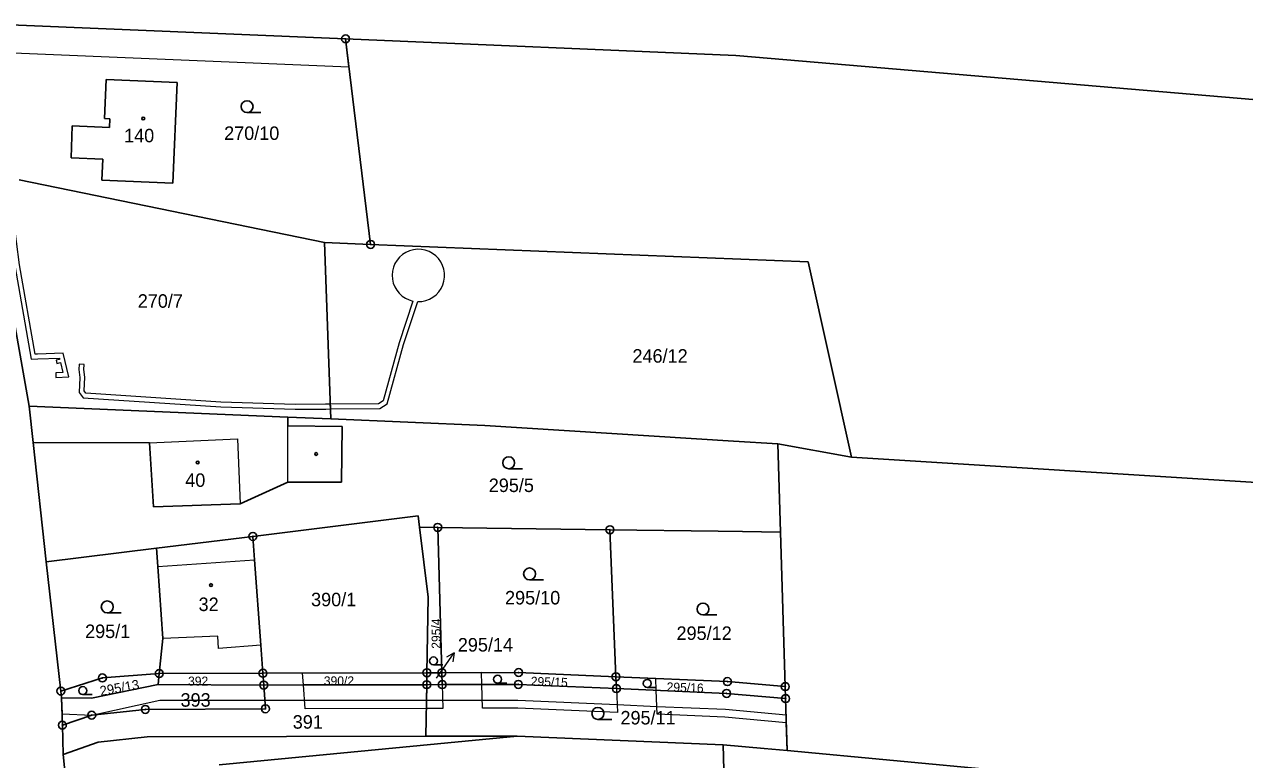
# Model space of a CAD drawing. Extents: x -645290 to -643454, y -1064771 to -1062356.
# Drawn here: x -644577 to -644423.3, y -1063574.3 to -1063481.7 of the extents above; entities that cross this region are included whole.
import ezdxf
from ezdxf.enums import TextEntityAlignment as Align

# ---------------------------------------------------------------- set-up
doc = ezdxf.new("R2010")
doc.units = 0
doc.header["$LTSCALE"] = 0.68
for name, color, linetype, lineweight in [('1', 7, 'Continuous', 25), ('13', 7, 'Continuous', 13), ('3', 7, 'Continuous', 25), ('4', 7, 'Continuous', 13), ('5', 7, 'Continuous', 25), ('7', 7, 'Continuous', 13), ('8', 7, 'Continuous', 25)]:
    doc.layers.add(name, color=color, linetype=linetype, lineweight=lineweight)
doc.layers.add('2', color=7, linetype='Continuous')

msp = doc.modelspace()

# ---------------------------------------------------------------- linework, layer by layer
at = {"layer": '1'}
for p, q in [((-644579.79, -1063481.67), (-644536.58, -1063483.49)), ((-644536.58, -1063483.49), (-644533.43, -1063509.39)), ((-644536.58, -1063483.49), (-644487.41, -1063485.57)), ((-644487.41, -1063485.57), (-644392.24, -1063493.71)), ((-644566.96, -1063493.51), (-644566.75, -1063488.62)), ((-644566.75, -1063488.62), (-644557.79, -1063489)), ((-644557.79, -1063489), (-644558.32, -1063501.68)), ((-644566.27, -1063493.55), (-644566.96, -1063493.51)), ((-644566.32, -1063494.66), (-644566.27, -1063493.55)), ((-644571.15, -1063498.5), (-644571.01, -1063494.45)), ((-644571.01, -1063494.45), (-644566.32, -1063494.66)), ((-644567.16, -1063498.66), (-644571.15, -1063498.5)), ((-644567.29, -1063501.28), (-644567.16, -1063498.66)), ((-644577.69, -1063501.25), (-644539.22, -1063509.16)), ((-644558.32, -1063501.68), (-644567.29, -1063501.28)), ((-644580.6, -1063506.24), (-644576.45, -1063529.78)), ((-644533.43, -1063509.39), (-644539.22, -1063509.16)), ((-644539.22, -1063509.16), (-644538.44, -1063531.37)), ((-644478.32, -1063511.57), (-644533.43, -1063509.39)), ((-644472.86, -1063536.21), (-644478.32, -1063511.57)), ((-644576.45, -1063529.78), (-644575.94, -1063534.35)), ((-644543.84, -1063531.14), (-644576.45, -1063529.78)), ((-644543.85, -1063532.23), (-644543.84, -1063531.14)), ((-644536.99, -1063532.32), (-644543.85, -1063532.23)), ((-644538.44, -1063531.37), (-644543.84, -1063531.14)), ((-644538.44, -1063531.37), (-644519.04, -1063532.18)), ((-644537.08, -1063539.34), (-644536.99, -1063532.32)), ((-644519.04, -1063532.18), (-644487.72, -1063534.16)), ((-644575.94, -1063534.35), (-644574.28, -1063549.38)), ((-644575.94, -1063534.35), (-644561.26, -1063534.39)), ((-644561.26, -1063534.39), (-644560.78, -1063542.45)), ((-644482.13, -1063534.51), (-644487.72, -1063534.16)), ((-644482.13, -1063534.51), (-644472.86, -1063536.21)), ((-644482.13, -1063534.51), (-644481.79, -1063545.62)), ((-644472.86, -1063536.21), (-644385.25, -1063541.67)), ((-644549.86, -1063542.06), (-644543.86, -1063539.32)), ((-644543.86, -1063539.32), (-644537.08, -1063539.34)), ((-644560.78, -1063542.45), (-644549.86, -1063542.06)), ((-644548.26, -1063546.17), (-644527.42, -1063543.6)), ((-644527.42, -1063543.6), (-644527.25, -1063545.01)), ((-644527.25, -1063545.01), (-644526.18, -1063553.83)), ((-644527.25, -1063545.01), (-644524.97, -1063545.04)), ((-644524.45, -1063563.34), (-644524.97, -1063545.04)), ((-644524.97, -1063545.04), (-644503.29, -1063545.33)), ((-644503.29, -1063545.33), (-644502.53, -1063563.85)), ((-644503.29, -1063545.33), (-644489.67, -1063545.52)), ((-644481.2, -1063565.1), (-644481.79, -1063545.62)), ((-644574.28, -1063549.38), (-644560.39, -1063547.67)), ((-644560.39, -1063547.67), (-644548.26, -1063546.17)), ((-644560.23, -1063549.96), (-644560.39, -1063547.67)), ((-644548.26, -1063546.17), (-644548.04, -1063549.14)), ((-644548.04, -1063549.14), (-644547.25, -1063559.89)), ((-644559.59, -1063559.05), (-644560.23, -1063549.96)), ((-644526.33, -1063563.35), (-644526.18, -1063553.83)), ((-644560.04, -1063563.44), (-644559.59, -1063559.05)), ((-644546.99, -1063563.41), (-644547.25, -1063559.89)), ((-644572.44, -1063565.65), (-644567.21, -1063564)), ((-644567.21, -1063564), (-644560.04, -1063563.44)), ((-644560.18, -1063564.82), (-644560.04, -1063563.44)), ((-644560.04, -1063563.44), (-644546.99, -1063563.41)), ((-644546.99, -1063563.41), (-644526.33, -1063563.35)), ((-644546.89, -1063564.9), (-644546.99, -1063563.41)), ((-644526.36, -1063564.85), (-644526.33, -1063563.35)), ((-644526.33, -1063563.35), (-644524.45, -1063563.34)), ((-644524.45, -1063563.34), (-644514.79, -1063563.32)), ((-644524.4, -1063564.84), (-644524.45, -1063563.34)), ((-644514.79, -1063563.32), (-644502.53, -1063563.85)), ((-644502.53, -1063563.85), (-644502.47, -1063565.35)), ((-644502.53, -1063563.85), (-644488.48, -1063564.46)), ((-644488.48, -1063564.46), (-644481.2, -1063565.1)), ((-644568.58, -1063566.54), (-644560.18, -1063564.82)), ((-644560.18, -1063564.82), (-644546.89, -1063564.9)), ((-644546.89, -1063564.9), (-644526.36, -1063564.85)), ((-644546.67, -1063567.89), (-644546.89, -1063564.9)), ((-644526.46, -1063571.35), (-644526.36, -1063564.85)), ((-644526.36, -1063564.85), (-644524.4, -1063564.84)), ((-644524.4, -1063564.84), (-644514.82, -1063564.82)), ((-644514.82, -1063564.82), (-644502.47, -1063565.35)), ((-644502.47, -1063565.35), (-644488.59, -1063565.95)), ((-644488.59, -1063565.95), (-644481.16, -1063566.61)), ((-644481.16, -1063566.61), (-644481.2, -1063565.1)), ((-644572.34, -1063566.51), (-644568.58, -1063566.54)), ((-644572.34, -1063566.51), (-644572.25, -1063569.95)), ((-644480.96, -1063573.16), (-644481.16, -1063566.61)), ((-644572.25, -1063569.95), (-644568.55, -1063568.69)), ((-644568.55, -1063568.69), (-644561.8, -1063567.97)), ((-644561.8, -1063567.97), (-644546.67, -1063567.89)), ((-644572.25, -1063569.95), (-644572.16, -1063573.65)), ((-644572.16, -1063573.65), (-644567.73, -1063572.1)), ((-644567.73, -1063572.1), (-644561.58, -1063571.44)), ((-644561.58, -1063571.44), (-644526.46, -1063571.35)), ((-644552.52, -1063574.93), (-644514.96, -1063571.32)), ((-644526.46, -1063571.35), (-644514.96, -1063571.32)), ((-644514.96, -1063571.32), (-644489.03, -1063572.44)), ((-644572.16, -1063573.65), (-644570.58, -1063588.42)), ((-644488.95, -1063575.57), (-644489.03, -1063572.44)), ((-644489.03, -1063572.44), (-644483.85, -1063572.9)), ((-644480.96, -1063573.16), (-644483.85, -1063572.9)), ((-644480.96, -1063573.16), (-644454.17, -1063575.65))]:
    msp.add_line(p, q, dxfattribs=at)
for points in [[(-644489.67, -1063545.52), (-644486.58, -1063545.56), (-644481.79, -1063545.62)], [(-644572.34, -1063566.51), (-644572.44, -1063565.65), (-644574.28, -1063549.38)]]:
    msp.add_lwpolyline(points, dxfattribs=at)
at = {"layer": '13'}
for points in [[(-644536.58, -1063483.49), (-644579.79, -1063481.67), (-644579.41, -1063485.19), (-644536.15, -1063487.01)], [(-644578.8, -1063503.15), (-644579.29, -1063503.99), (-644578.24, -1063512.03), (-644576.17, -1063523.83), (-644575.34, -1063523.8), (-644572.63, -1063523.71), (-644572.59, -1063523.88), (-644573.02, -1063523.99), (-644572.93, -1063524.37), (-644572.5, -1063524.26), (-644572.2, -1063525.52), (-644573.09, -1063525.56), (-644573.07, -1063526.16), (-644571.44, -1063526.09), (-644572.16, -1063523.09), (-644575.39, -1063523.2), (-644575.67, -1063523.21), (-644577.64, -1063511.94)], [(-644529.85, -1063521.8), (-644531.86, -1063529.08), (-644532.44, -1063529.47), (-644538.5, -1063529.52), (-644538.48, -1063530.12), (-644532.25, -1063530.07), (-644531.34, -1063529.45), (-644529.27, -1063521.98), (-644527.48, -1063516.59), (-644526.978, -1063516.562), (-644526.486, -1063516.459), (-644526.016, -1063516.282), (-644525.578, -1063516.035), (-644525.183, -1063515.725), (-644524.839, -1063515.359), (-644524.555, -1063514.944), (-644524.337, -1063514.492), (-644524.19, -1063514.011), (-644524.118, -1063513.514), (-644524.122, -1063513.011), (-644524.203, -1063512.515), (-644524.357, -1063512.037), (-644524.583, -1063511.588), (-644524.874, -1063511.179), (-644525.224, -1063510.818), (-644525.625, -1063510.515), (-644526.067, -1063510.276), (-644526.541, -1063510.107), (-644527.034, -1063510.012), (-644527.536, -1063509.993), (-644528.036, -1063510.05), (-644528.52, -1063510.183), (-644528.979, -1063510.387), (-644529.402, -1063510.659), (-644529.778, -1063510.992), (-644530.1, -1063511.378), (-644530.359, -1063511.809), (-644530.55, -1063512.274), (-644530.668, -1063512.762), (-644530.711, -1063513.263), (-644530.676, -1063513.764), (-644530.567, -1063514.255), (-644530.384, -1063514.723), (-644530.132, -1063515.157), (-644529.817, -1063515.549), (-644529.446, -1063515.888), (-644529.028, -1063516.167), (-644528.572, -1063516.379), (-644528.09, -1063516.52)], [(-644570.12, -1063524.48), (-644570.16, -1063525.16), (-644570.03, -1063526.15), (-644570.13, -1063528.04), (-644569.62, -1063528.7), (-644552.3, -1063529.85), (-644542.94, -1063530.16), (-644539.06, -1063530.13), (-644538.48, -1063530.12), (-644538.5, -1063529.52), (-644539.1, -1063529.53), (-644542.94, -1063529.56), (-644552.27, -1063529.25), (-644569.3, -1063528.12), (-644569.52, -1063527.85), (-644569.43, -1063526.13), (-644569.56, -1063525.14), (-644569.52, -1063524.52)], [(-644502.38, -1063567.36), (-644497.37, -1063567.58), (-644488.72, -1063567.95), (-644481.1, -1063568.63), (-644481.16, -1063566.61), (-644488.59, -1063565.95), (-644497.46, -1063565.57), (-644502.47, -1063565.35), (-644514.82, -1063564.82), (-644519.4, -1063564.83), (-644519.44, -1063563.33), (-644524.45, -1063563.34), (-644524.4, -1063564.84), (-644526.36, -1063564.85), (-644541.88, -1063564.89), (-644546.89, -1063564.9), (-644560.18, -1063564.82), (-644568.58, -1063566.54), (-644572.34, -1063566.51), (-644572.29, -1063568.51), (-644568.55, -1063568.69), (-644559.99, -1063566.82), (-644546.75, -1063566.82), (-644541.73, -1063566.82), (-644526.39, -1063566.82), (-644524.35, -1063566.82), (-644519.35, -1063566.82), (-644514.87, -1063566.82)], [(-644559.99, -1063566.82), (-644546.75, -1063566.82), (-644541.73, -1063566.82), (-644526.39, -1063566.82), (-644526.36, -1063564.85), (-644541.88, -1063564.89), (-644541.99, -1063563.4), (-644546.99, -1063563.41), (-644546.89, -1063564.9), (-644560.18, -1063564.82), (-644568.58, -1063566.54), (-644572.34, -1063566.51), (-644572.29, -1063568.51), (-644568.55, -1063568.69)], [(-644497.52, -1063564.07), (-644502.53, -1063563.85), (-644502.47, -1063565.35), (-644514.82, -1063564.82), (-644519.4, -1063564.83), (-644524.4, -1063564.84), (-644526.36, -1063564.85), (-644541.88, -1063564.89), (-644546.89, -1063564.9), (-644560.18, -1063564.82), (-644568.58, -1063566.54), (-644572.34, -1063566.51), (-644572.29, -1063568.51), (-644568.55, -1063568.69), (-644559.99, -1063566.82), (-644546.75, -1063566.82), (-644541.73, -1063566.82), (-644526.39, -1063566.82), (-644524.35, -1063566.82), (-644519.35, -1063566.82), (-644514.87, -1063566.82), (-644502.38, -1063567.36), (-644497.37, -1063567.58), (-644488.72, -1063567.95), (-644481.1, -1063568.63), (-644481.16, -1063566.61), (-644488.59, -1063565.95), (-644497.46, -1063565.57)], [(-644519.32, -1063567.83), (-644519.4, -1063564.83), (-644519.44, -1063563.33), (-644524.45, -1063563.34), (-644524.4, -1063564.84), (-644524.32, -1063567.84), (-644526.4, -1063567.85), (-644541.65, -1063567.88), (-644541.88, -1063564.89), (-644546.89, -1063564.9), (-644546.67, -1063567.89), (-644561.8, -1063567.97), (-644568.55, -1063568.69), (-644572.25, -1063569.95), (-644572.16, -1063573.65), (-644567.73, -1063572.1), (-644561.58, -1063571.44), (-644526.46, -1063571.35), (-644514.96, -1063571.32), (-644489.03, -1063572.44), (-644483.85, -1063572.9), (-644480.96, -1063573.16), (-644481.07, -1063569.64), (-644488.8, -1063568.95), (-644497.33, -1063568.58), (-644497.46, -1063565.57), (-644502.47, -1063565.35), (-644502.34, -1063568.37), (-644514.89, -1063567.82)], [(-644541.65, -1063567.88), (-644541.88, -1063564.89), (-644541.99, -1063563.4), (-644546.99, -1063563.41), (-644546.89, -1063564.9), (-644546.67, -1063567.89), (-644561.8, -1063567.97), (-644568.55, -1063568.69), (-644572.25, -1063569.95), (-644572.16, -1063573.65), (-644567.73, -1063572.1), (-644561.58, -1063571.44), (-644526.46, -1063571.35), (-644526.4, -1063567.85)], [(-644497.52, -1063564.07), (-644502.53, -1063563.85), (-644502.47, -1063565.35), (-644502.34, -1063568.37), (-644514.89, -1063567.82), (-644519.32, -1063567.83), (-644519.4, -1063564.83), (-644524.4, -1063564.84), (-644524.32, -1063567.84), (-644526.4, -1063567.85), (-644541.65, -1063567.88), (-644541.88, -1063564.89), (-644546.89, -1063564.9), (-644546.67, -1063567.89), (-644561.8, -1063567.97), (-644568.55, -1063568.69), (-644572.25, -1063569.95), (-644572.16, -1063573.65), (-644567.73, -1063572.1), (-644561.58, -1063571.44), (-644526.46, -1063571.35), (-644514.96, -1063571.32), (-644489.03, -1063572.44), (-644483.85, -1063572.9), (-644480.96, -1063573.16), (-644481.07, -1063569.64), (-644488.8, -1063568.95), (-644497.33, -1063568.58), (-644497.46, -1063565.57)], [(-644488.72, -1063567.95), (-644481.1, -1063568.63), (-644481.16, -1063566.61), (-644488.59, -1063565.95), (-644497.46, -1063565.57), (-644502.47, -1063565.35), (-644514.82, -1063564.82), (-644519.4, -1063564.83), (-644524.4, -1063564.84), (-644526.36, -1063564.85), (-644541.88, -1063564.89), (-644546.89, -1063564.9), (-644560.18, -1063564.82), (-644568.58, -1063566.54), (-644572.34, -1063566.51), (-644572.29, -1063568.51), (-644568.55, -1063568.69), (-644559.99, -1063566.82), (-644546.75, -1063566.82), (-644541.73, -1063566.82), (-644526.39, -1063566.82), (-644524.35, -1063566.82), (-644519.35, -1063566.82), (-644514.87, -1063566.82), (-644502.38, -1063567.36), (-644497.37, -1063567.58)], [(-644488.8, -1063568.95), (-644497.33, -1063568.58), (-644497.46, -1063565.57), (-644502.47, -1063565.35), (-644502.34, -1063568.37), (-644514.89, -1063567.82), (-644519.32, -1063567.83), (-644519.4, -1063564.83), (-644524.4, -1063564.84), (-644524.32, -1063567.84), (-644526.4, -1063567.85), (-644541.65, -1063567.88), (-644541.88, -1063564.89), (-644546.89, -1063564.9), (-644546.67, -1063567.89), (-644561.8, -1063567.97), (-644568.55, -1063568.69), (-644572.25, -1063569.95), (-644572.16, -1063573.65), (-644567.73, -1063572.1), (-644561.58, -1063571.44), (-644526.46, -1063571.35), (-644514.96, -1063571.32), (-644489.03, -1063572.44), (-644483.85, -1063572.9), (-644480.96, -1063573.16), (-644481.07, -1063569.64)]]:
    msp.add_lwpolyline(points, close=True, dxfattribs=at)
at = {"layer": '3'}
for p, q in [((-644548.983, -1063492.78), (-644547.233, -1063492.78)), ((-644516.033, -1063537.65), (-644514.283, -1063537.65)), ((-644513.403, -1063551.65), (-644511.653, -1063551.65)), ((-644566.593, -1063555.8), (-644564.843, -1063555.8)), ((-644491.563, -1063556.07), (-644489.813, -1063556.07)), ((-644525.505, -1063562.36), (-644524.333, -1063562.36)), ((-644569.675, -1063566.1), (-644568.503, -1063566.1)), ((-644517.435, -1063564.67), (-644516.263, -1063564.67)), ((-644498.585, -1063565.2), (-644497.413, -1063565.2)), ((-644504.803, -1063569.23), (-644503.053, -1063569.23))]:
    msp.add_line(p, q, dxfattribs=at)
for centre, radius in [((-644548.9829, -1063492.0298), 0.75), ((-644516.0329, -1063536.8998), 0.75), ((-644513.4029, -1063550.8998), 0.75), ((-644566.5929, -1063555.0498), 0.75), ((-644491.5629, -1063555.3198), 0.75), ((-644525.5052, -1063561.8574), 0.5025), ((-644517.4352, -1063564.1674), 0.5025), ((-644498.5852, -1063564.6974), 0.5025), ((-644569.6752, -1063565.5974), 0.5025), ((-644504.8029, -1063568.4798), 0.75)]:
    msp.add_circle(centre, radius, dxfattribs=at)
at = {"layer": '4'}
for p, q in [((-644543.86, -1063539.32), (-644543.85, -1063532.23)), ((-644561.26, -1063534.39), (-644550.18, -1063533.86)), ((-644550.18, -1063533.86), (-644549.86, -1063542.06)), ((-644560.23, -1063549.96), (-644548.04, -1063549.14)), ((-644552.66, -1063558.72), (-644559.59, -1063559.05)), ((-644552.59, -1063560.29), (-644552.66, -1063558.72)), ((-644547.25, -1063559.89), (-644552.59, -1063560.29))]:
    msp.add_line(p, q, dxfattribs=at)
at = {"layer": '5'}
for centre in [(-644562.0568, -1063493.5292), (-644555.2068, -1063536.8692), (-644540.2968, -1063535.7892), (-644553.5268, -1063552.2992)]:
    msp.add_circle(centre, 0.175, dxfattribs=at)
at = {"layer": '7'}
msp.add_line((-644522.889, -1063560.852), (-644523.873, -1063561.385), dxfattribs=at)
msp.add_lwpolyline([(-644525.11, -1063564.02), (-644524.61, -1063563.31), (-644522.889, -1063560.852), (-644523.053, -1063561.959)], dxfattribs=at)
at = {"layer": '8'}
for centre, radius in [((-644536.58, -1063483.4899), 0.5), ((-644536.58, -1063483.4899), 0.0303), ((-644533.43, -1063509.3899), 0.5), ((-644533.43, -1063509.3899), 0.0303), ((-644524.97, -1063545.0399), 0.5), ((-644548.26, -1063546.1699), 0.5), ((-644548.26, -1063546.1699), 0.0303), ((-644524.97, -1063545.0399), 0.0303), ((-644503.29, -1063545.3299), 0.5), ((-644503.29, -1063545.3299), 0.0303), ((-644560.04, -1063563.4399), 0.5), ((-644546.99, -1063563.4099), 0.5), ((-644526.33, -1063563.3499), 0.5), ((-644524.45, -1063563.3399), 0.5), ((-644514.79, -1063563.3199), 0.5), ((-644567.21, -1063563.9999), 0.5), ((-644567.21, -1063563.9999), 0.0303), ((-644560.04, -1063563.4399), 0.0303), ((-644546.89, -1063564.8999), 0.5), ((-644546.99, -1063563.4099), 0.0303), ((-644526.36, -1063564.8499), 0.5), ((-644526.33, -1063563.3499), 0.0303), ((-644524.4, -1063564.8399), 0.5), ((-644524.45, -1063563.3399), 0.0303), ((-644514.82, -1063564.8199), 0.5), ((-644514.79, -1063563.3199), 0.0303), ((-644502.53, -1063563.8499), 0.5), ((-644502.53, -1063563.8499), 0.0303), ((-644488.48, -1063564.4599), 0.5), ((-644488.48, -1063564.4599), 0.0303), ((-644572.44, -1063565.6499), 0.5), ((-644572.44, -1063565.6499), 0.0303), ((-644546.89, -1063564.8999), 0.0303), ((-644526.36, -1063564.8499), 0.0303), ((-644524.4, -1063564.8399), 0.0303), ((-644514.82, -1063564.8199), 0.0303), ((-644502.47, -1063565.3499), 0.5), ((-644502.47, -1063565.3499), 0.0303), ((-644488.59, -1063565.9499), 0.5), ((-644488.59, -1063565.9499), 0.0303), ((-644481.2, -1063565.0999), 0.5), ((-644481.16, -1063566.6099), 0.5), ((-644481.2, -1063565.0999), 0.0303), ((-644561.8, -1063567.9699), 0.5), ((-644546.67, -1063567.8899), 0.5), ((-644481.16, -1063566.6099), 0.0303), ((-644568.55, -1063568.6899), 0.5), ((-644568.55, -1063568.6899), 0.0303), ((-644561.8, -1063567.9699), 0.0303), ((-644546.67, -1063567.8899), 0.0303), ((-644572.25, -1063569.9499), 0.5), ((-644572.25, -1063569.9499), 0.0303)]:
    msp.add_circle(centre, radius, dxfattribs=at)

# ---------------------------------------------------------------- texts
at = {"layer": '2'}
for s, height, p in [('140', 1.7, (-644562.579, -1063496.525)), ('270/10', 1.7, (-644548.4, -1063496.225)), ('270/7', 1.7, (-644559.91, -1063517.365)), ('246/12', 1.7, (-644496.97, -1063524.285)), ('40', 1.7, (-644555.509, -1063539.935)), ('295/5', 1.7, (-644515.7, -1063540.584)), ('390/1', 1.7, (-644538.08, -1063554.975)), ('295/10', 1.7, (-644513.02, -1063554.745)), ('32', 1.7, (-644553.829, -1063555.574)), ('295/1', 1.7, (-644566.54, -1063558.975)), ('295/12', 1.7, (-644491.42, -1063559.215)), ('392', 1.139, (-644555.149, -1063564.974)), ('393', 1.7, (-644555.469, -1063567.625)), ('391', 1.7, (-644541.339, -1063570.395)), ('295/11', 1.7, (-644498.48, -1063569.865))]:
    msp.add_text(s, height=height, dxfattribs=at).set_placement(p, align=Align.CENTER)
for s, height, rotation, p in [('295/4', 1.139, 90, (-644524.605, -1063558.42)), ('295/13', 1.224, 10, (-644564.9518, -1063565.841))]:
    msp.add_text(s, height=height, rotation=rotation, dxfattribs=at).set_placement(p, align=Align.CENTER)
for s, height, p in [('295/14', 1.7, (-644522.44, -1063560.675)), ('390/2', 1.139, (-644539.32, -1063564.944))]:
    msp.add_text(s, height=height, dxfattribs=at).set_placement(p)
for s, p in [('295/15', (-644513.269, -1063564.984)), ('295/16', (-644496.159, -1063565.694))]:
    msp.add_text(s, height=1.139, rotation=358, dxfattribs=at).set_placement(p)

doc.saveas('drawing.dxf')
